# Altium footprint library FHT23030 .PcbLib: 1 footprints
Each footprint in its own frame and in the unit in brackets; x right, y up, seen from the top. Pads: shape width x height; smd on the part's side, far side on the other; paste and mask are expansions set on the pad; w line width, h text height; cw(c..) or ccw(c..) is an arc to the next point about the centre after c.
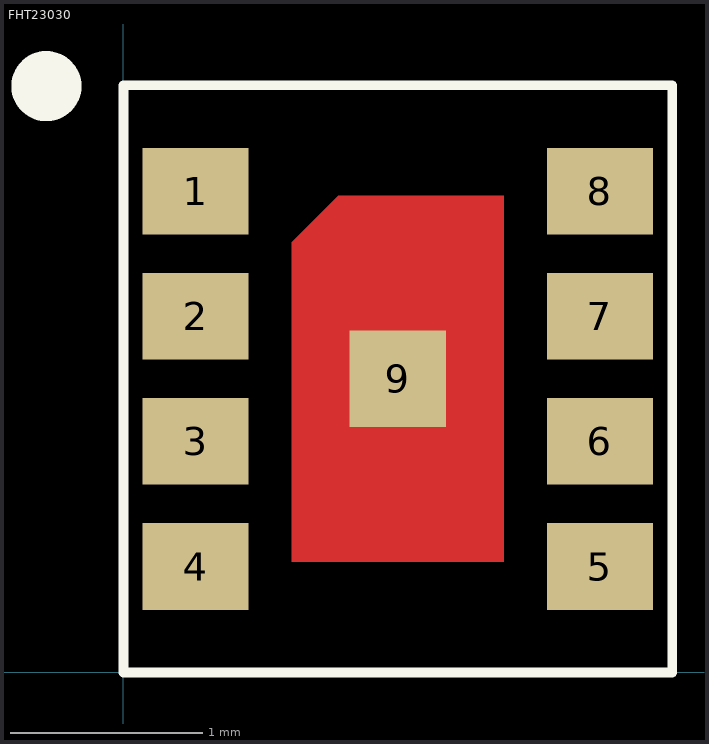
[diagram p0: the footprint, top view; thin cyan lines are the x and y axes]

## FHT23030 [mm]
pads (9):
  rect 0.55x0.45 smd paste-0.05 mask-0.051: 1(0.375,2.5) 2(0.375,1.85) 3(0.375,1.2) 4(0.375,0.55) 5(2.475,0.55) 6(2.475,1.2) 7(2.475,1.85) 8(2.475,2.5)
  rect 0.5x0.5 smd paste-0.6 mask-0.051: 9(1.425,1.525)
Top Layer:
  region: 0.875,0.575 1.975,0.575 1.975,2.475 1.115,2.475 0.875,2.235
Top Overlay:
  circle w0.254: c-0.4,3.045 r0.055
  lines w0.05: 0,0 0,3.05 2.85,3.05 2.85,0 0,0
Top Paste:
  region: 0.875,0.575 1.975,0.575 1.975,2.475 1.115,2.475 0.875,2.235
Top Solder:
  region: 0.875,0.575 1.975,0.575 1.975,2.475 1.115,2.475 0.875,2.235
3D body: height 1.57, standoff 0, extent 0,0 2.85,3.05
